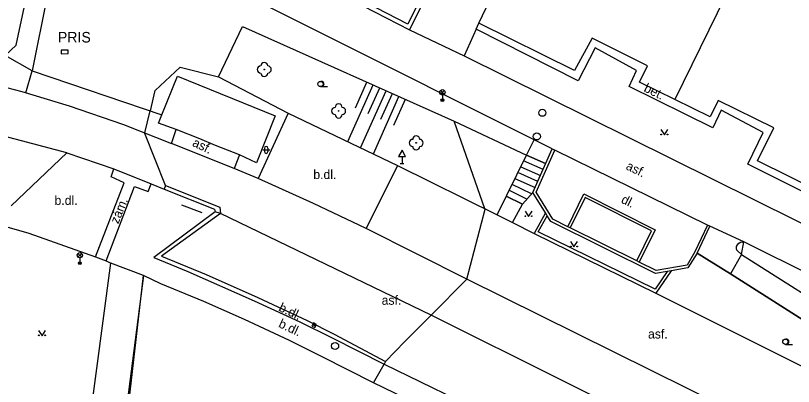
# Model space of a CAD drawing. Extents: x -602419 to -601554, y -1162937 to -1162362.
# Drawn here: x -602308.5 to -602253.1, y -1162519.4 to -1162493.1 of the extents above; entities that cross this region are included whole.
import ezdxf

# ---------------------------------------------------------------- set-up
doc = ezdxf.new("R2010")
doc.units = 0
doc.layers.add('Podklad', color=7, linetype='Continuous')

msp = doc.modelspace()

# ---------------------------------------------------------------- linework, layer by layer
at = {"layer": 'Podklad'}
for p, q in [((-602286.79, -1162498.1275), (-602286.29, -1162498.1275)), ((-602278.2525, -1162498.66), (-602277.9875, -1162498.395)), ((-602278.2525, -1162498.395), (-602277.9875, -1162498.66)), ((-602278.12, -1162498.715), (-602278.12, -1162499.09)), ((-602290.903, -1162502.628), (-602290.403, -1162502.628)), ((-602290.778, -1162502.503), (-602290.778, -1162502.753)), ((-602290.528, -1162502.503), (-602290.528, -1162502.753)), ((-602280.99, -1162503.091), (-602280.99, -1162503.6)), ((-602281.115, -1162503.6), (-602280.865, -1162503.6)), ((-602304.0424, -1162510.25), (-602303.7774, -1162509.985)), ((-602304.0424, -1162509.985), (-602303.7774, -1162510.25)), ((-602303.9099, -1162510.305), (-602303.9099, -1162510.68)), ((-602287.3518, -1162515.0441), (-602287.1282, -1162515.1559)), ((-602253.7199, -1162516.4575), (-602253.2199, -1162516.4575))]:
    msp.add_line(p, q, dxfattribs=at)
for points in [[(-602271.59, -1162501.9099), (-602302, -1162486.6599)], [(-602256.15, -1162487.95), (-602261.59, -1162499.04)], [(-602285.04, -1162491.37), (-602284.1599, -1162489.57), (-602279.67, -1162491.84), (-602280.58, -1162493.69), (-602285.04, -1162491.37)], [(-602304.83, -1162502.84), (-602311.77, -1162501.0069), (-602317.2, -1162500.0369), (-602396.05, -1162491.38)], [(-602309.2199, -1162495.9099), (-602308.45, -1162495.19), (-602307.64, -1162491.38)], [(-602306.24, -1162491.68), (-602307.29, -1162497.01)], [(-602285.44, -1162491.5), (-602280.45, -1162494.1)], [(-602280.45, -1162494.1), (-602279.27, -1162491.71)], [(-602275.53, -1162493.62), (-602275, -1162492.53)], [(-602297.81, -1162505.1599), (-602299.29, -1162501.4599), (-602299.2797, -1162501.4168), (-602298.8962, -1162499.8504), (-602298.894, -1162499.8409), (-602298.54, -1162498.3939), (-602296.761, -1162496.749), (-602294.04, -1162497.43), (-602292.34, -1162493.85)], [(-602292.34, -1162493.85), (-602277.28, -1162500.58), (-602272.13, -1162503)], [(-602275.7199, -1162494.04), (-602275.53, -1162493.62)], [(-602268.71, -1162496.9699), (-602275.53, -1162493.62)], [(-602280.45, -1162494.1), (-602276.56, -1162495.95)], [(-602275.7199, -1162494.04), (-602276.56, -1162495.95)], [(-602249.13, -1162507.26), (-602256.38, -1162503.64), (-602255.3, -1162501.4), (-602258.28, -1162499.81), (-602258.89, -1162501.06), (-602264.84, -1162498.12), (-602264.3, -1162496.98), (-602267.25, -1162495.37), (-602268.46, -1162497.71), (-602275.7199, -1162494.04)], [(-602267.46, -1162494.69), (-602268.71, -1162496.9699)], [(-602263.52, -1162496.64), (-602267.46, -1162494.69)], [(-602307.7449, -1162498.5654), (-602307.29, -1162497.01), (-602309.2199, -1162495.9099)], [(-602276.56, -1162495.95), (-602250.04, -1162509.09)], [(-602264.09, -1162497.8), (-602263.52, -1162496.64)], [(-602316.63, -1162496.73), (-602314.4, -1162497.05), (-602311.34, -1162497.61), (-602308.03, -1162498.48), (-602304.6599, -1162499.49), (-602300.81, -1162500.81), (-602297.38, -1162502.17)], [(-602307.29, -1162497.01), (-602298.07, -1162500.13)], [(-602298.07, -1162500.13), (-602296.9699, -1162497.38)], [(-602296.9699, -1162497.38), (-602290.01, -1162500.2)], [(-602294.04, -1162497.43), (-602289.08, -1162500.01)], [(-602284.31, -1162499.64), (-602283.49, -1162497.8)], [(-602261.59, -1162499.04), (-602264.09, -1162497.8)], [(-602284.84, -1162502.04), (-602283.04, -1162498.01)], [(-602283.4, -1162500.05), (-602282.58, -1162498.21)], [(-602283.94, -1162502.48), (-602282.12, -1162498.42)], [(-602283.03, -1162502.9099), (-602281.21, -1162498.82)], [(-602282.49, -1162500.45), (-602281.67, -1162498.62)], [(-602281.57, -1162500.86), (-602280.75, -1162499.03)], [(-602259.07, -1162500.28), (-602261.59, -1162499.04)], [(-602258.5, -1162499.12), (-602259.07, -1162500.28)], [(-602254.55, -1162501.07), (-602258.5, -1162499.12)], [(-602289.08, -1162500.01), (-602291.23, -1162504.67)], [(-602289.08, -1162500.01), (-602281.32, -1162503.73)], [(-602298.31, -1162500.73), (-602298.07, -1162500.13)], [(-602290.01, -1162500.2), (-602291.35, -1162503.55)], [(-602278.919, -1162514.3799), (-602276.39, -1162511.82), (-602275.0801, -1162506.8499), (-602275.0931, -1162506.8127), (-602277.28, -1162500.58)], [(-602297.06, -1162501.17), (-602298.31, -1162500.73)], [(-602255.71, -1162503.4), (-602254.55, -1162501.07)], [(-602297.38, -1162502.17), (-602297.06, -1162501.17)], [(-602295.37, -1162501.85), (-602297.06, -1162501.17)], [(-602262.58, -1162501.185), (-602262.33, -1162501.56), (-602262.08, -1162501.185)], [(-602292.94, -1162503.94), (-602297.38, -1162502.17)], [(-602294.26, -1162502.31), (-602295.37, -1162501.85)], [(-602272.13, -1162503), (-602271.59, -1162501.9099)], [(-602270.31, -1162502.55), (-602271.59, -1162501.9099)], [(-602292.55, -1162502.9699), (-602294.26, -1162502.31)], [(-602271.69, -1162505.6599), (-602270.31, -1162502.55)], [(-602269.2, -1162508.09), (-602270.27, -1162507.56), (-602271.46, -1162505.64), (-602270.13, -1162502.64)], [(-602270.31, -1162502.55), (-602270.13, -1162502.64)], [(-602259.27, -1162507.9699), (-602270.13, -1162502.64)], [(-602308.8, -1162506.6), (-602304.83, -1162502.84)], [(-602304.83, -1162502.84), (-602301.48, -1162503.9699)], [(-602292.55, -1162502.9699), (-602292.94, -1162503.94)], [(-602291.35, -1162503.55), (-602292.55, -1162502.9699)], [(-602274.23, -1162507.24), (-602272.13, -1162503)], [(-602270.7766, -1162503.6015), (-602272.13, -1162503)], [(-602272.13, -1162503), (-602270.78, -1162503.6)], [(-602281.32, -1162503.73), (-602283.55, -1162508.2199)], [(-602281.32, -1162503.73), (-602274.23, -1162507.24)], [(-602272.55, -1162503.83), (-602271.15, -1162504.45)], [(-602270.96, -1162504.02), (-602272.34, -1162503.4099)], [(-602248.89, -1162506.77), (-602255.71, -1162503.4)], [(-602302.8, -1162510.24), (-602300.75, -1162504.96), (-602301.67, -1162504.54), (-602301.48, -1162503.9699)], [(-602301.48, -1162503.9699), (-602298.83, -1162505.03)], [(-602291.23, -1162504.67), (-602292.94, -1162503.94)], [(-602271.34, -1162504.87), (-602272.75, -1162504.24)], [(-602283.55, -1162508.2199), (-602287.29, -1162506.44), (-602291.23, -1162504.67)], [(-602272.96, -1162504.6599), (-602271.53, -1162505.3)], [(-602324.35, -1162505.52), (-602316.4699, -1162506.42), (-602311.85, -1162507.32), (-602307.53, -1162508.55), (-602302.8, -1162510.24)], [(-602302.04, -1162510.52), (-602300.02, -1162505.2199), (-602299.06, -1162505.58), (-602298.83, -1162505.03)], [(-602298.83, -1162505.03), (-602297.9099, -1162505.43), (-602294.33, -1162506.84)], [(-602297.81, -1162505.1599), (-602293.94, -1162506.69), (-602293.9099, -1162507.1599), (-602298.09, -1162510.18), (-602294.93, -1162511.49), (-602291.25, -1162513.13), (-602287.74, -1162514.77), (-602285.82, -1162515.73), (-602282.17, -1162517.67)], [(-602297.81, -1162505.1599), (-602297.91, -1162505.43)], [(-602273.37, -1162505.49), (-602272.1, -1162506.12)], [(-602271.78, -1162505.76), (-602273.1599, -1162505.08)], [(-602272.4099, -1162506.49), (-602273.58, -1162505.9099)], [(-602273.573, -1162505.9134), (-602272.4099, -1162506.49)], [(-602273.14, -1162507.79), (-602272.4099, -1162506.49), (-602271.69, -1162505.6599)], [(-602270.78, -1162507.11), (-602271.69, -1162505.6599)], [(-602269.2, -1162508.09), (-602268.05, -1162505.76), (-602262.99, -1162508.3), (-602264.11, -1162510.61)], [(-602264.29, -1162510.52), (-602263.25, -1162508.39), (-602267.96, -1162506.02), (-602269.02, -1162508.18)], [(-602296.68, -1162506.54), (-602295.2199, -1162507.08)], [(-602294.33, -1162506.84), (-602294.28, -1162507.02), (-602298.65, -1162510.29)], [(-602278.919, -1162514.3799), (-602293.9099, -1162507.1599), (-602294.28, -1162507.02)], [(-602272.24, -1162506.995), (-602271.99, -1162507.37), (-602271.74, -1162506.995)], [(-602270.78, -1162507.11), (-602271.59, -1162508.57)], [(-602270.6599, -1162507.31), (-602270.78, -1162507.11)], [(-602274.23, -1162507.24), (-602273.14, -1162507.79)], [(-602262.12, -1162511.27), (-602262.99, -1162512.54), (-602271.3, -1162508.45), (-602270.6599, -1162507.31)], [(-602262.12, -1162511.27), (-602262.95, -1162511.4099), (-602270.4099, -1162507.71), (-602270.6599, -1162507.31)], [(-602239.67, -1162530.01), (-602276.39, -1162511.82), (-602283.55, -1162508.2199)], [(-602273.14, -1162507.79), (-602271.59, -1162508.57)], [(-602269.02, -1162508.18), (-602269.2, -1162508.09)], [(-602264.29, -1162510.52), (-602269.02, -1162508.18)], [(-602259.27, -1162507.9699), (-602260.1599, -1162509.87), (-602260.7, -1162510.82), (-602262.92, -1162511.2), (-602264.11, -1162510.61)], [(-602259.99, -1162509.9699), (-602259.09, -1162508.05)], [(-602259.09, -1162508.05), (-602259.27, -1162507.9699)], [(-602256.83, -1162510.07), (-602256.67, -1162509.17), (-602259.09, -1162508.05)], [(-602271.59, -1162508.57), (-602262.94, -1162512.82)], [(-602269.01, -1162509.145), (-602268.76, -1162509.52), (-602268.51, -1162509.145)], [(-602257.17, -1162509.75), (-602257.2, -1162509.63), (-602257.19, -1162509.5), (-602257.13, -1162509.37), (-602257.04, -1162509.26), (-602256.92, -1162509.19), (-602256.79, -1162509.1599), (-602256.67, -1162509.17)], [(-602226.79, -1162524.32), (-602226.71, -1162524.07), (-602256.67, -1162509.17)], [(-602259.99, -1162509.9699), (-602260.67, -1162511.02), (-602261.85, -1162511.2199)], [(-602259.99, -1162509.9699), (-602257.62, -1162511.44)], [(-602257.62, -1162511.44), (-602259.99, -1162509.9699)], [(-602257.17, -1162509.75), (-602256.83, -1162510.07)], [(-602302.8, -1162510.24), (-602302.04, -1162510.52)], [(-602302.04, -1162510.52), (-602301.71, -1162510.68)], [(-602298.65, -1162510.29), (-602296.2199, -1162511.27), (-602291.51, -1162513.35)], [(-602264.11, -1162510.61), (-602264.29, -1162510.52)], [(-602256.83, -1162510.07), (-602257.62, -1162511.44)], [(-602256.83, -1162510.07), (-602248.75, -1162515.18)], [(-602304.33, -1162530.4699), (-602301.71, -1162510.68)], [(-602299.39, -1162511.57), (-602301.71, -1162510.68)], [(-602299.39, -1162511.57), (-602300.85, -1162522.96)], [(-602300.69, -1162522.94), (-602299.39, -1162511.57)], [(-602257.9099, -1162531.68), (-602258.37, -1162531.44), (-602259.79, -1162530.71), (-602260.81, -1162530.2), (-602275.4699, -1162522.85), (-602283.02, -1162519.18), (-602286.67, -1162517.34), (-602289, -1162516.17), (-602292.19, -1162514.68), (-602295.08, -1162513.4), (-602298.14, -1162512.15), (-602299.39, -1162511.57)], [(-602261.85, -1162511.2199), (-602262.94, -1162512.82)], [(-602261.85, -1162511.2199), (-602262.12, -1162511.27)], [(-602257.62, -1162511.44), (-602248.9, -1162516.99), (-602236.98, -1162524.59)], [(-602248.9, -1162516.99), (-602257.62, -1162511.44)], [(-602262.94, -1162512.82), (-602237.5, -1162525.53)], [(-602291.51, -1162513.35), (-602288.25, -1162514.86), (-602285.95, -1162516)], [(-602282.17, -1162517.67), (-602280.779, -1162516.2619), (-602278.919, -1162514.3799)], [(-602260.1, -1162523.77), (-602278.919, -1162514.3799)], [(-602306.85, -1162515.465), (-602306.6, -1162515.84), (-602306.35, -1162515.465)], [(-602285.95, -1162516), (-602282.27, -1162517.87), (-602274.56, -1162521.6)], [(-602282.17, -1162517.67), (-602282.27, -1162517.87)], [(-602283.02, -1162519.18), (-602282.27, -1162517.87)]]:
    msp.add_lwpolyline(points, dxfattribs=at)
for points in [[(-602305.2364, -1162495.7919), (-602304.7366, -1162495.7778), (-602304.7436, -1162495.5279), (-602305.2434, -1162495.542)], [(-602281.24, -1162503.091), (-602280.74, -1162503.091), (-602280.99, -1162502.658)], [(-602287.4077, -1162515.156), (-602287.184, -1162515.2677), (-602287.0723, -1162515.044), (-602287.296, -1162514.9323)]]:
    msp.add_lwpolyline(points, close=True, dxfattribs=at)
for centre, radius in [((-602290.79, -1162496.9099), 0.025), ((-602286.79, -1162497.9398), 0.1875), ((-602278.12, -1162498.5275), 0.1875), ((-602278.12, -1162499.09), 0.1), ((-602278.12, -1162499.09), 0.0723), ((-602278.12, -1162499.09), 0.0438), ((-602285.5, -1162499.86), 0.025), ((-602271.01, -1162499.99), 0.25), ((-602271.4, -1162501.67), 0.25), ((-602262.5551, -1162501.5349), 0.025), ((-602262.1054, -1162501.5349), 0.025), ((-602279.98, -1162502.13), 0.025), ((-602272.2151, -1162507.3449), 0.025), ((-602271.7654, -1162507.3449), 0.025), ((-602303.9099, -1162510.1175), 0.1875), ((-602268.9851, -1162509.4949), 0.025), ((-602268.5354, -1162509.4949), 0.025), ((-602303.9099, -1162510.68), 0.1), ((-602303.9099, -1162510.68), 0.0723), ((-602303.9099, -1162510.68), 0.0438), ((-602306.8251, -1162515.8149), 0.025), ((-602306.3754, -1162515.8149), 0.025), ((-602253.7199, -1162516.2698), 0.1875), ((-602285.75, -1162516.57), 0.25)]:
    msp.add_circle(centre, radius, dxfattribs=at)
for centre, radius, start, end in [((-602291.04, -1162496.9099), 0.25, 90, 270), ((-602290.79, -1162496.6599), 0.25, 0, 180), ((-602290.54, -1162496.9099), 0.25, 270, 90), ((-602290.79, -1162497.1599), 0.25, 180, 0), ((-602286.7275, -1162497.9398), 0.1875, 260.40593, 99.59407), ((-602285.5, -1162499.61), 0.25, 0, 180), ((-602285.75, -1162499.86), 0.25, 90, 270), ((-602285.25, -1162499.86), 0.25, 270, 90), ((-602285.5, -1162500.11), 0.25, 180, 0), ((-602279.98, -1162501.88), 0.25, 0, 180), ((-602280.23, -1162502.13), 0.25, 90, 270), ((-602279.73, -1162502.13), 0.25, 270, 90), ((-602290.6528, -1162502.5031), 0.125, 0, 180), ((-602290.6528, -1162502.7531), 0.125, 180, 0), ((-602279.98, -1162502.38), 0.25, 180, 0), ((-602253.6574, -1162516.2698), 0.1875, 260.40593, 99.59407)]:
    msp.add_arc(centre, radius, start, end, dxfattribs=at)

# ---------------------------------------------------------------- texts
for s, height, p in [('PRIS', 0.75, (-602305.4699, -1162494.99)), ('b.dl.', 0.65, (-602287.3, -1162504.7)), ('b.dl.', 0.65, (-602305.71, -1162506.54)), ('asf.', 0.65, (-602282.44, -1162513.64)), ('asf.', 0.65, (-602263.49, -1162516.04))]:
    msp.add_text(s, height=height, dxfattribs=at).set_placement(p)
for s, rotation, p in [('bet.', 333.74, (-602263.84, -1162498.44)), ('asf.', 334.73, (-602295.96, -1162502.33)), ('asf.', 333.86, (-602265.12, -1162503.98)), ('dl.', 333.34, (-602265.46, -1162506.36)), ('zám.', 67.69, (-602301.18, -1162507.93)), ('b.dl.', 334.59, (-602289.82, -1162514.05)), ('b.dl.', 334.59, (-602289.83, -1162515.2))]:
    msp.add_text(s, height=0.65, rotation=rotation, dxfattribs=at).set_placement(p)

doc.saveas('drawing.dxf')
